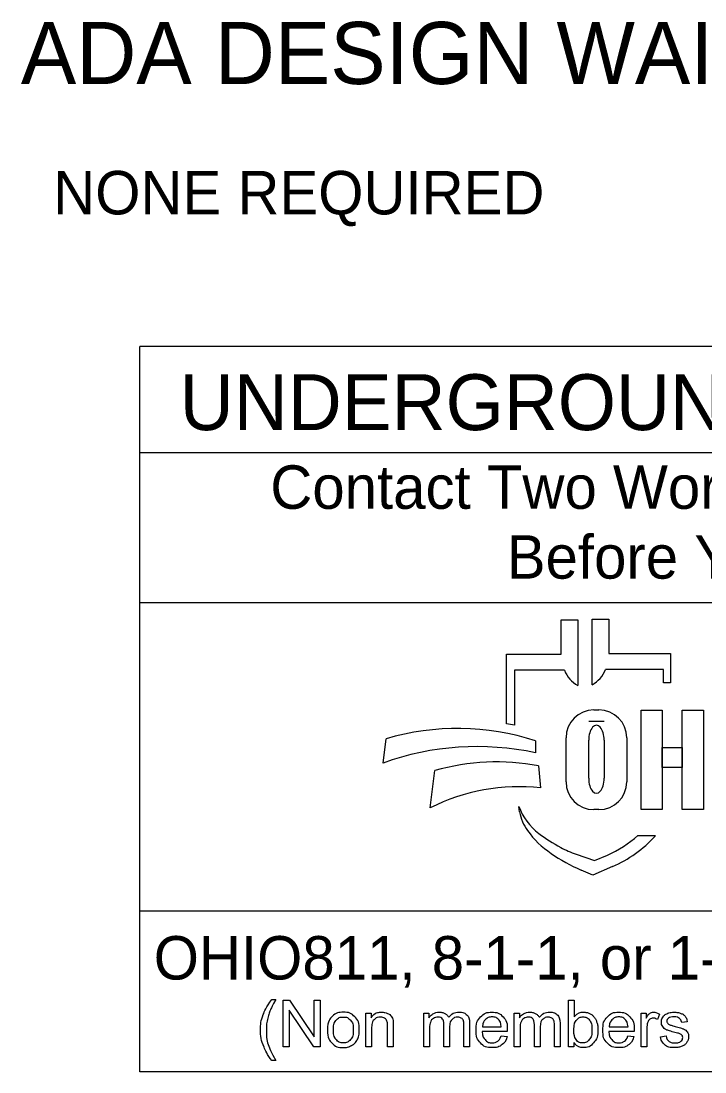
# Model space of a CAD drawing. Extents: x 0 to 34, y 0 to 22.
# Drawn here: x 1.995 to 4.196, y 2.143 to 5.529 of the extents above; entities that cross this region are included whole.
import ezdxf

# ---------------------------------------------------------------- set-up
doc = ezdxf.new("R2010")
doc.units = 0
doc.layers.add('SH_Border', color=7, linetype='Continuous')
doc.layers.add('SH_Cut_Line', color=7, linetype='Continuous')

msp = doc.modelspace()

# ---------------------------------------------------------------- linework, layer by layer
at = {"layer": 'SH_Border'}
for p, q in [((3.7335, 3.4883), (3.7335, 3.5998)), ((3.7335, 3.5998), (3.7872, 3.5998)), ((3.7872, 3.5998), (3.7872, 3.3877)), ((3.8329, 3.39), (3.8329, 3.6021)), ((3.8329, 3.6021), (3.8865, 3.6021)), ((3.8865, 3.6021), (3.8865, 3.4906)), ((3.5576, 3.2644), (3.5576, 3.4883)), ((3.5576, 3.4883), (3.7335, 3.4883)), ((3.8865, 3.4906), (4.0857, 3.4906)), ((4.0857, 3.4906), (4.0857, 3.3968)), ((3.5828, 3.4369), (3.5828, 3.26)), ((3.7439, 3.4369), (3.5828, 3.4369)), ((4.0625, 3.4392), (3.8761, 3.4392)), ((4.0625, 3.3968), (4.0625, 3.4392)), ((4.0857, 3.3968), (4.0625, 3.3968)), ((3.8385, 3.3091), (3.8551, 3.3091)), ((3.8718, 3.2721), (3.822, 3.2721)), ((3.7491, 3.0776), (3.7491, 3.2196)), ((3.9445, 3.2196), (3.9445, 3.0776)), ((3.1602, 3.1381), (3.1696, 3.2162)), ((3.6509, 3.2097), (3.6509, 3.1709)), ((3.822, 3.089), (3.822, 3.2114)), ((3.8718, 3.2114), (3.8718, 3.089)), ((3.6608, 3.1291), (3.6671, 3.0582)), ((3.312, 2.9936), (3.3267, 3.1137)), ((3.5997, 2.9807), (3.5967, 2.9986)), ((3.8551, 2.9882), (3.8385, 2.9882)), ((3.98, 2.9048), (4.0375, 2.9048)), ((3.7816, 2.8444), (3.841, 2.8239)), ((3.841, 2.8239), (3.8821, 2.8417)), ((3.835, 2.7769), (3.7976, 2.7934)), ((3.8983, 2.8044), (3.835, 2.7769))]:
    msp.add_line(p, q, dxfattribs=at)
for points in [[(3.991, 3.3081), (4.0589, 3.3081), (4.0589, 2.9881), (3.991, 2.9881)], [(4.1231, 3.3081), (4.1911, 3.3081), (4.1911, 2.9881), (4.1231, 2.9881)], [(4.0589, 3.1882), (4.1231, 3.1882), (4.1231, 3.1242), (4.0589, 3.1242)]]:
    msp.add_lwpolyline(points, close=True, dxfattribs=at)
for points in [[(2.8021, 2.3766), (2.8153, 2.3766)], [(2.8389, 2.2239), (2.8389, 2.3741), (2.8592, 2.3741), (2.9382, 2.2561), (2.9382, 2.3741), (2.9572, 2.3741), (2.9572, 2.2239), (2.9369, 2.2239), (2.8579, 2.3419), (2.8579, 2.2239), (2.8389, 2.2239)], [(3.7743, 2.2239), (3.7573, 2.2239), (3.7573, 2.3741), (3.7757, 2.3741), (3.7757, 2.3206)], [(3.1048, 2.2239), (3.1048, 2.3328), (3.1214, 2.3328), (3.1214, 2.3173)], [(3.2912, 2.2239), (3.2912, 2.3328), (3.3077, 2.3328), (3.3077, 2.3174)], [(3.5826, 2.2239), (3.5826, 2.3328), (3.5991, 2.3328), (3.5991, 2.3174)], [(3.9904, 2.2239), (3.9904, 2.3328), (4.007, 2.3328), (4.007, 2.3163)], [(4.0495, 2.3293), (4.043, 2.3122)], [(4.1394, 2.3046), (4.1213, 2.3022)], [(3.1233, 2.2833), (3.1233, 2.2239), (3.1048, 2.2239)], [(3.1932, 2.2908), (3.1932, 2.2239), (3.1748, 2.2239), (3.1748, 2.2901)], [(3.3097, 2.2803), (3.3097, 2.2239), (3.2912, 2.2239)], [(3.3743, 2.2871), (3.3743, 2.2239), (3.3559, 2.2239), (3.3559, 2.2946)], [(3.4388, 2.2986), (3.4388, 2.2239), (3.4203, 2.2239), (3.4203, 2.2924)], [(3.56, 2.2736), (3.4788, 2.2736)], [(3.4799, 2.2887), (3.5406, 2.2887)], [(3.601, 2.2803), (3.601, 2.2239), (3.5826, 2.2239)], [(3.6657, 2.2871), (3.6657, 2.2239), (3.6473, 2.2239), (3.6473, 2.2946)], [(3.7301, 2.2986), (3.7301, 2.2239), (3.7117, 2.2239), (3.7117, 2.2924)], [(3.968, 2.2736), (3.8868, 2.2736)], [(3.8879, 2.2887), (3.9486, 2.2887)], [(4.0088, 2.2809), (4.0088, 2.2239), (3.9904, 2.2239)], [(3.5404, 2.2591), (3.5595, 2.2567)], [(3.7743, 2.2375), (3.7743, 2.2239)], [(3.9484, 2.2591), (3.9675, 2.2567)], [(4.053, 2.2564), (4.0712, 2.2593)], [(2.8153, 2.1798), (2.8021, 2.1798)]]:
    msp.add_lwpolyline(points, dxfattribs=at)
for centre, radius, start, end in [((3.8353, 3.4736), 0.0985, 201.9296, 240.7469), ((3.7847, 3.476), 0.0985, 299.2531, 338.0704), ((3.8385, 3.2196), 0.0895, 90, 180), ((3.8551, 3.2196), 0.0895, 0, 90), ((3.4295, 2.4554), 0.8191, 79.2074, 81.0007), ((3.3997, 2.4302), 0.8191, 72.1402, 106.3144), ((3.4628, 2.2991), 0.8919, 77.8238, 109.8274), ((3.5267, 2.4094), 0.7322, 79.44, 105.8467), ((3.5987, 2.4262), 0.6357, 83.8248, 116.8021), ((3.8385, 3.0776), 0.0895, 180, 270), ((3.8551, 3.0776), 0.0895, 270, 0), ((3.7841, 3.0707), 0.2008, 201.0457, 232.5314), ((3.741, 3.0048), 0.1433, 189.6817, 216.0884), ((3.8747, 3.1022), 0.3088, 216.0884, 235.7167), ((3.9766, 3.3219), 0.5173, 232.5314, 241.794), ((3.7387, 3.1722), 0.3602, 293.4582, 312.0712), ((3.7387, 3.1722), 0.401, 293.4582, 317.8286), ((4.0412, 3.3465), 0.6044, 235.7167, 246.2325), ((3.8914, 3.1631), 0.3371, 241.794, 250.9821)]:
    msp.add_arc(centre, radius, start, end, dxfattribs=at)
for centre, start_param, end_param in [((3.8469, 3.2114), 4.712389, 7.853982), ((3.8469, 3.089), 1.570796, 4.712389)]:
    msp.add_ellipse(centre, major_axis=(0, 0.0484), ratio=0.514403, start_param=start_param, end_param=end_param, dxfattribs=at)
for points in [[(2.8021, 2.1798), (2.7869, 2.199), (2.7763, 2.2248), (2.7657, 2.2506), (2.7657, 2.2783), (2.7657, 2.3026), (2.7736, 2.325), (2.7829, 2.3509), (2.8021, 2.3766)], [(2.8153, 2.3766), (2.8029, 2.3553), (2.7989, 2.3462), (2.7927, 2.332), (2.7891, 2.3167), (2.7847, 2.2975), (2.7847, 2.2782), (2.7847, 2.2289), (2.8153, 2.1798)], [(2.9814, 2.2783), (2.9814, 2.3085), (2.9981, 2.3231), (3.0122, 2.3352), (3.0323, 2.3352), (3.0547, 2.3352), (3.069, 2.3205), (3.0832, 2.3058), (3.0832, 2.2799), (3.0832, 2.2589), (3.0769, 2.2469), (3.0706, 2.2348), (3.0586, 2.2282), (3.0466, 2.2215), (3.0323, 2.2215), (3.0095, 2.2215), (2.9954, 2.2362), (2.9814, 2.2508), (2.9814, 2.2783)], [(3.0003, 2.2783), (3.0003, 2.2574), (3.0094, 2.247), (3.0185, 2.2366), (3.0323, 2.2366), (3.046, 2.2366), (3.0551, 2.2471), (3.0642, 2.2575), (3.0642, 2.279), (3.0642, 2.2991), (3.0551, 2.3095), (3.0459, 2.3199), (3.0323, 2.3199), (3.0185, 2.3199), (3.0094, 2.3096), (3.0003, 2.2992), (3.0003, 2.2783)], [(3.1214, 2.3173), (3.1334, 2.3352), (3.156, 2.3352), (3.1659, 2.3352), (3.1741, 2.3316), (3.1823, 2.3281), (3.1864, 2.3224), (3.1905, 2.3166), (3.1922, 2.3087), (3.1932, 2.3036), (3.1932, 2.2908)], [(3.1748, 2.2901), (3.1748, 2.3013), (3.1726, 2.3069), (3.1705, 2.3125), (3.165, 2.3158), (3.1595, 2.3191), (3.1521, 2.3191), (3.1404, 2.3191), (3.1318, 2.3117), (3.1233, 2.3042), (3.1233, 2.2833)], [(3.3077, 2.3174), (3.3128, 2.3254), (3.3214, 2.3303), (3.3299, 2.3352), (3.3407, 2.3352), (3.3528, 2.3352), (3.3606, 2.3301), (3.3683, 2.3251), (3.3715, 2.3161), (3.3844, 2.3352), (3.4051, 2.3352), (3.4213, 2.3352), (3.43, 2.3262), (3.4388, 2.3172), (3.4388, 2.2986)], [(3.3559, 2.2946), (3.3559, 2.3069), (3.3514, 2.313), (3.3469, 2.3191), (3.3366, 2.3191), (3.3288, 2.3191), (3.3222, 2.315), (3.3156, 2.311), (3.3126, 2.3031), (3.3097, 2.2952), (3.3097, 2.2803)], [(3.4203, 2.2924), (3.4203, 2.3035), (3.4185, 2.3083), (3.4168, 2.3132), (3.412, 2.3162), (3.4073, 2.3191), (3.401, 2.3191), (3.3895, 2.3191), (3.3819, 2.3115), (3.3743, 2.3039), (3.3743, 2.2871)], [(3.5595, 2.2567), (3.555, 2.24), (3.5428, 2.2307), (3.5306, 2.2215), (3.5117, 2.2215), (3.4878, 2.2215), (3.4738, 2.2362), (3.4598, 2.2509), (3.4598, 2.2774), (3.4598, 2.3049), (3.474, 2.32), (3.4881, 2.3352), (3.5106, 2.3352), (3.5324, 2.3352), (3.5463, 2.3203), (3.5601, 2.3055), (3.5601, 2.2785), (3.5601, 2.2769), (3.56, 2.2736)], [(3.5406, 2.2887), (3.5394, 2.3025), (3.5337, 2.3094), (3.5249, 2.3201), (3.5108, 2.3201), (3.4981, 2.3201), (3.4894, 2.3115), (3.4808, 2.303), (3.4799, 2.2887)], [(3.5991, 2.3174), (3.6042, 2.3254), (3.6127, 2.3303), (3.6212, 2.3352), (3.6321, 2.3352), (3.6442, 2.3352), (3.6519, 2.3301), (3.6597, 2.3251), (3.6628, 2.3161), (3.6758, 2.3352), (3.6965, 2.3352), (3.7127, 2.3352), (3.7214, 2.3262), (3.7301, 2.3172), (3.7301, 2.2986)], [(3.6473, 2.2946), (3.6473, 2.3069), (3.6428, 2.313), (3.6383, 2.3191), (3.628, 2.3191), (3.6202, 2.3191), (3.6136, 2.315), (3.607, 2.311), (3.604, 2.3031), (3.601, 2.2952), (3.601, 2.2803)], [(3.7117, 2.2924), (3.7117, 2.3035), (3.7099, 2.3083), (3.7081, 2.3132), (3.7034, 2.3162), (3.6987, 2.3191), (3.6923, 2.3191), (3.6809, 2.3191), (3.6733, 2.3115), (3.6657, 2.3039), (3.6657, 2.2871)], [(3.7741, 2.2792), (3.7741, 2.2596), (3.7794, 2.2509), (3.7881, 2.2366), (3.8029, 2.2366), (3.815, 2.2366), (3.8238, 2.2471), (3.8326, 2.2576), (3.8326, 2.2784), (3.8326, 2.2998), (3.8241, 2.3099), (3.8157, 2.3201), (3.8038, 2.3201), (3.7917, 2.3201), (3.7829, 2.3096), (3.7741, 2.299), (3.7741, 2.2792)], [(3.7757, 2.3206), (3.7874, 2.3352), (3.8055, 2.3352), (3.8155, 2.3352), (3.8245, 2.3311), (3.8335, 2.3271), (3.8392, 2.3198), (3.845, 2.3124), (3.8483, 2.3021), (3.8516, 2.2918), (3.8516, 2.28), (3.8516, 2.252), (3.8378, 2.2368), (3.8239, 2.2215), (3.8046, 2.2215), (3.7853, 2.2215), (3.7743, 2.2375)], [(3.9675, 2.2567), (3.963, 2.24), (3.9508, 2.2307), (3.9386, 2.2215), (3.9196, 2.2215), (3.8958, 2.2215), (3.8818, 2.2362), (3.8678, 2.2509), (3.8678, 2.2774), (3.8678, 2.3049), (3.882, 2.32), (3.8961, 2.3352), (3.9186, 2.3352), (3.9404, 2.3352), (3.9543, 2.3203), (3.9681, 2.3055), (3.9681, 2.2785), (3.9681, 2.2769), (3.968, 2.2736)], [(3.9486, 2.2887), (3.9474, 2.3025), (3.9417, 2.3094), (3.9328, 2.3201), (3.9188, 2.3201), (3.9061, 2.3201), (3.8974, 2.3115), (3.8888, 2.303), (3.8879, 2.2887)], [(4.007, 2.3163), (4.0133, 2.3278), (4.0187, 2.3315), (4.0241, 2.3352), (4.0305, 2.3352), (4.0398, 2.3352), (4.0495, 2.3293)], [(4.043, 2.3122), (4.0363, 2.3162), (4.0295, 2.3162), (4.0235, 2.3162), (4.0187, 2.3125), (4.0139, 2.3089), (4.0119, 2.3024), (4.0088, 2.2926), (4.0088, 2.2809)], [(4.1213, 2.3022), (4.1201, 2.3106), (4.1142, 2.3153), (4.1083, 2.3201), (4.0975, 2.3201), (4.0848, 2.3201), (4.0794, 2.3159), (4.0739, 2.3116), (4.0739, 2.306), (4.0739, 2.3024), (4.0762, 2.2995), (4.0785, 2.2966), (4.0833, 2.2946), (4.086, 2.2936), (4.0996, 2.2899), (4.1192, 2.2847), (4.1269, 2.2813), (4.1347, 2.278), (4.1391, 2.2717), (4.1435, 2.2653), (4.1435, 2.2559), (4.1435, 2.2467), (4.1381, 2.2386), (4.1327, 2.2304), (4.1226, 2.226), (4.1124, 2.2215), (4.0996, 2.2215), (4.0784, 2.2215), (4.0672, 2.2303), (4.0561, 2.2391), (4.053, 2.2564)], [(4.0712, 2.2593), (4.0727, 2.2483), (4.0798, 2.2425), (4.0868, 2.2366), (4.0995, 2.2366), (4.1122, 2.2366), (4.1184, 2.2418), (4.1245, 2.247), (4.1245, 2.254), (4.1245, 2.2602), (4.1191, 2.2638), (4.1153, 2.2663), (4.1002, 2.2701), (4.0799, 2.2752), (4.072, 2.2789), (4.0642, 2.2827), (4.0601, 2.2893), (4.0561, 2.2959), (4.0561, 2.3038), (4.0561, 2.3111), (4.0594, 2.3173), (4.0628, 2.3235), (4.0685, 2.3276), (4.0728, 2.3308), (4.0803, 2.333), (4.0877, 2.3352), (4.0962, 2.3352), (4.109, 2.3352), (4.1187, 2.3315), (4.1284, 2.3278), (4.133, 2.3215), (4.1377, 2.3152), (4.1394, 2.3046)], [(3.4788, 2.2736), (3.4799, 2.2557), (3.489, 2.2462), (3.4981, 2.2366), (3.5117, 2.2366), (3.5219, 2.2366), (3.5291, 2.242), (3.5362, 2.2473), (3.5404, 2.2591)], [(3.8868, 2.2736), (3.8879, 2.2557), (3.897, 2.2462), (3.9061, 2.2366), (3.9197, 2.2366), (3.9299, 2.2366), (3.937, 2.242), (3.9442, 2.2473), (3.9484, 2.2591)]]:
    msp.add_open_spline(points, degree=3, dxfattribs=at)
at = {"layer": 'SH_Cut_Line'}
for p, q in [((2.3775, 2.1428), (2.3775, 4.4803)), ((6.6275, 4.4803), (2.3775, 4.4803)), ((2.3775, 4.1387), (6.6275, 4.1387)), ((2.3775, 3.6553), (6.6275, 3.6553)), ((6.6275, 2.6607), (2.3775, 2.6607)), ((6.6275, 2.1428), (2.3775, 2.1428))]:
    msp.add_line(p, q, dxfattribs=at)

# ---------------------------------------------------------------- texts
at = {"layer": 'SH_Border'}
for s, height, p in [('ADA DESIGN WAIVERS', 0.2, (1.9944, 5.3256)), ('  NONE REQUIRED                          ', 0.14, (1.9944, 4.9056)), ('UNDERGROUND UTILITIES', 0.18, (2.5057, 4.2106)), ('Contact Two Working Days', 0.14, (2.7972, 3.9571)), ('Before You Dig', 0.14, (3.5583, 3.7321)), ('OHIO811, 8-1-1, or 1-800-362-2764', 0.14, (2.422, 2.4406))]:
    msp.add_text(s, height=height, dxfattribs=at).set_placement(p)

doc.saveas('drawing.dxf')
